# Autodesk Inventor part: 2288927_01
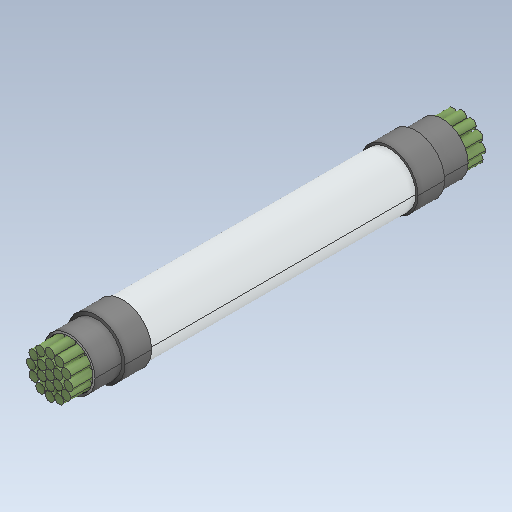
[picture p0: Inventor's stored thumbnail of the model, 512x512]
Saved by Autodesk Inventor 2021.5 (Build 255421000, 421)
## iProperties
Created: 2026-04
Part Number: 2288927_01
Checked By: TraceParts S.A.
Material: Generic
Catalog Web Link: www.traceparts.com
Document SubType Name: Modeling
Designer: TraceParts
Density: 1 g/cm^3
Appearance: Default
Company: TraceParts S.A.
Author: TraceParts
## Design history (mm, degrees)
feature "2288927_01.ipt"
body "Solid1"
